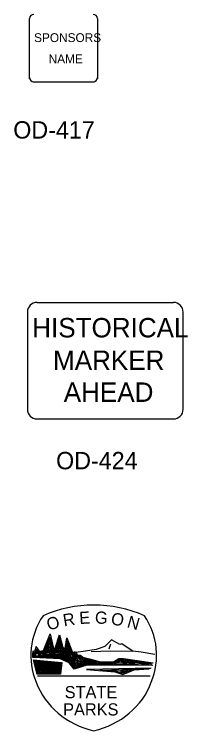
# Model space of a CAD drawing. Extents: x 42133 to 45533, y 41351 to 47951.
# Drawn here: x 42779.6 to 42854.3, y 44951.7 to 45261.2 of the extents above; entities that cross this region are included whole.
import ezdxf

# ---------------------------------------------------------------- set-up
doc = ezdxf.new("R2010")
doc.units = 0
doc.layers.add('P_TRAF_SIGN_SignDetails', color=7, linetype='Continuous')

msp = doc.modelspace()

# ---------------------------------------------------------------- linework, layer by layer
at = {"layer": 'P_TRAF_SIGN_SignDetails'}
for p, q in [((42786.11, 45233.28), (42786.11, 45259.36)), ((42815.43, 45259.36), (42815.43, 45233.33)), ((42787.69, 45232.03), (42814.06, 45232.03)), ((42789.42, 45136.71), (42848.16, 45136.71)), ((42785.22, 45132.52), (42785.22, 45090.56)), ((42852.35, 45090.56), (42852.35, 45132.52)), ((42789.42, 45086.36), (42848.16, 45086.36)), ((42792.22, 44986.34), (42795.01, 44993.48)), ((42794.9, 44992.08), (42792.65, 44986.21)), ((42794.79, 44990.77), (42793.04, 44985.99)), ((42796.31, 44986.62), (42794.79, 44990.77)), ((42796.36, 44986.93), (42794.9, 44992.08)), ((42795.01, 44993.48), (42796.55, 44987.19)), ((42797.19, 44987.33), (42799.06, 44993.15)), ((42798.95, 44991.87), (42797.43, 44987.04)), ((42800.25, 44987.19), (42798.95, 44991.87)), ((42799.06, 44993.15), (42800.53, 44987.58)), ((42801.51, 44987.12), (42802.17, 44991.83)), ((42802.17, 44991.83), (42804.7, 44985.42)), ((42821.53, 44990.96), (42818.54, 44988.02)), ((42825, 44988.87), (42821.53, 44990.96)), ((42789.03, 44988.1), (42788.36, 44985.91)), ((42790.38, 44986.03), (42789.03, 44988.1)), ((42794.74, 44989.58), (42793.33, 44985.74)), ((42794.74, 44988.02), (42793.83, 44985.68)), ((42796.03, 44986.21), (42794.74, 44989.58)), ((42795.86, 44985.88), (42794.74, 44988.02)), ((42798.95, 44990.63), (42797.83, 44986.93)), ((42798.95, 44989.38), (42798.11, 44986.77)), ((42798.84, 44988.12), (42798.56, 44986.46)), ((42799.63, 44985.94), (42798.84, 44988.12)), ((42800.14, 44986.73), (42798.95, 44990.63)), ((42799.85, 44986.35), (42798.95, 44989.38)), ((42802.22, 44990.41), (42801.77, 44986.73)), ((42802.33, 44989.27), (42802.11, 44986.46)), ((42804.36, 44985.11), (42802.22, 44990.41)), ((42804.18, 44984.85), (42802.33, 44989.27)), ((42818.54, 44988.02), (42814.86, 44986.71)), ((42820.46, 44987.03), (42821.17, 44989.26)), ((42825.99, 44989.18), (42825, 44988.87)), ((42828.62, 44987.35), (42825.99, 44989.18)), ((42788.66, 44985.64), (42787.37, 44985.26)), ((42787.37, 44985.26), (42787.48, 44983.45)), ((42788.36, 44985.91), (42787.45, 44985.81)), ((42788.66, 44985.32), (42787.76, 44985)), ((42787.76, 44985), (42787.82, 44983.7)), ((42788.83, 44985), (42788.15, 44984.85)), ((42788.15, 44984.85), (42788.15, 44983.97)), ((42789.39, 44984.8), (42788.49, 44984.64)), ((42788.49, 44984.64), (42788.71, 44984.17)), ((42789.11, 44986.77), (42788.66, 44985.64)), ((42789.28, 44986.05), (42788.66, 44985.32)), ((42789.5, 44985.47), (42788.83, 44985)), ((42790.46, 44985.74), (42789.11, 44986.77)), ((42790.34, 44985.43), (42789.28, 44986.05)), ((42790.51, 44984.8), (42789.39, 44984.8)), ((42790.34, 44985.11), (42789.5, 44985.47)), ((42794.29, 44985.52), (42789.9, 44984.49)), ((42793.04, 44985.99), (42790.34, 44985.43)), ((42793.33, 44985.74), (42790.34, 44985.11)), ((42790.38, 44986.03), (42792.22, 44986.34)), ((42792.65, 44986.21), (42790.46, 44985.74)), ((42793.83, 44985.68), (42790.51, 44984.8)), ((42794.4, 44985.26), (42791.7, 44984.59)), ((42791.7, 44984.59), (42799.52, 44984.59)), ((42794.85, 44986.73), (42794.29, 44985.52)), ((42794.85, 44985.88), (42794.4, 44985.26)), ((42794.96, 44985.05), (42794.45, 44984.85)), ((42794.45, 44984.85), (42798.11, 44984.95)), ((42795.75, 44985.52), (42794.85, 44986.73)), ((42795.58, 44985.32), (42794.85, 44985.88)), ((42798.44, 44985.47), (42794.96, 44985.05)), ((42798.73, 44985.94), (42795.58, 44985.32)), ((42799.07, 44986.31), (42795.75, 44985.52)), ((42798.56, 44986.46), (42795.86, 44985.88)), ((42798.11, 44986.77), (42796.03, 44986.21)), ((42797.83, 44986.93), (42796.31, 44986.62)), ((42797.43, 44987.04), (42796.36, 44986.93)), ((42796.55, 44987.19), (42797.19, 44987.33)), ((42798.11, 44984.95), (42800.03, 44984.75)), ((42799.24, 44985), (42798.44, 44985.47)), ((42799.07, 44985.32), (42798.73, 44985.94)), ((42799.4, 44985.64), (42799.07, 44986.31)), ((42802.45, 44985.11), (42799.07, 44985.32)), ((42802.16, 44984.75), (42799.24, 44985)), ((42802.83, 44985.43), (42799.4, 44985.64)), ((42799.52, 44984.59), (42803.01, 44983.55)), ((42802.78, 44985.74), (42799.63, 44985.94)), ((42802.45, 44986.1), (42799.85, 44986.35)), ((42800.03, 44984.75), (42802.61, 44983.91)), ((42802.11, 44986.46), (42800.14, 44986.73)), ((42801.77, 44986.73), (42800.25, 44987.19)), ((42800.53, 44987.58), (42801.51, 44987.12)), ((42803.01, 44983.55), (42802.16, 44984.75)), ((42802.56, 44987.5), (42802.45, 44986.1)), ((42803.4, 44983.6), (42802.45, 44985.11)), ((42804.02, 44984.54), (42802.56, 44987.5)), ((42803.73, 44984.12), (42802.78, 44986.31)), ((42802.78, 44986.31), (42802.78, 44985.74)), ((42803.34, 44983.81), (42802.83, 44985.43)), ((42805.25, 44984.64), (42804.02, 44984.54)), ((42805.48, 44985.05), (42804.18, 44984.85)), ((42805.59, 44985.47), (42804.36, 44985.11)), ((42804.7, 44985.42), (42805.91, 44985.81)), ((42805.48, 44984.23), (42805.25, 44984.64)), ((42805.88, 44984.28), (42805.48, 44985.05)), ((42806.27, 44984.28), (42805.59, 44985.47)), ((42805.91, 44985.81), (42806.83, 44984.36)), ((42810.23, 44986), (42806.05, 44985.41)), ((42814.86, 44986.71), (42810.23, 44986)), ((42821.02, 44985.98), (42812.65, 44985.8)), ((42830.53, 44985.9), (42821.02, 44985.98)), ((42830.67, 44985.97), (42828.62, 44987.35)), ((42834.21, 44985.64), (42830.67, 44985.97)), ((42840.15, 44984.56), (42834.21, 44985.64)), ((42787.48, 44983.45), (42799.46, 44983.03)), ((42799.3, 44982.67), (42787.55, 44983.24)), ((42787.67, 44982.31), (42800.01, 44981.17)), ((42787.67, 44982.31), (42789.37, 44976.13)), ((42787.82, 44983.7), (42799.57, 44983.34)), ((42787.99, 44982), (42799.78, 44980.95)), ((42789.65, 44976.28), (42788.12, 44981.76)), ((42788.12, 44981.76), (42799.48, 44980.75)), ((42788.15, 44983.97), (42799.8, 44983.6)), ((42789.96, 44976.52), (42788.47, 44981.45)), ((42788.47, 44981.45), (42799.15, 44980.49)), ((42788.71, 44984.17), (42799.74, 44983.87)), ((42789.9, 44984.49), (42799.74, 44984.23)), ((42803.27, 44981.03), (42799.3, 44982.67)), ((42799.46, 44983.03), (42803.01, 44981.42)), ((42799.57, 44983.34), (42803.12, 44981.94)), ((42799.74, 44984.23), (42803.17, 44983.23)), ((42799.74, 44983.87), (42803.12, 44982.98)), ((42799.8, 44983.6), (42803.17, 44982.46)), ((42802.16, 44984.38), (42801.37, 44984.33)), ((42802.61, 44983.91), (42802.16, 44984.38)), ((42803.01, 44981.42), (42805.88, 44984.28)), ((42803.12, 44981.94), (42805.48, 44984.23)), ((42803.12, 44982.98), (42803.96, 44983.81)), ((42803.17, 44982.46), (42805.03, 44984.17)), ((42803.17, 44983.23), (42803.4, 44983.6)), ((42803.96, 44983.81), (42803.34, 44983.81)), ((42803.46, 44981.63), (42806.27, 44984.28)), ((42803.53, 44981.17), (42806.52, 44984.22)), ((42804.81, 44984.28), (42803.73, 44984.12)), ((42804.03, 44981.11), (42806.39, 44983.88)), ((42804.53, 44981.23), (42806.64, 44983.53)), ((42805.03, 44984.17), (42804.81, 44984.28)), ((42804.9, 44981.23), (42806.58, 44982.96)), ((42805.34, 44981.23), (42806.33, 44982.33)), ((42806.08, 44981.06), (42806.33, 44981.46)), ((42806.33, 44982.33), (42806.58, 44981.64)), ((42811, 44981.46), (42806.33, 44980.08)), ((42806.33, 44981.46), (42806.52, 44981)), ((42806.39, 44983.88), (42807.08, 44983.81)), ((42806.52, 44984.22), (42807.57, 44984.05)), ((42806.58, 44982.96), (42807.08, 44981.98)), ((42806.58, 44981.64), (42809.13, 44981.35)), ((42806.64, 44983.53), (42807.82, 44982.38)), ((42806.83, 44984.36), (42808.18, 44984.23)), ((42807.08, 44983.81), (42808.31, 44982.84)), ((42807.08, 44981.98), (42811, 44981.46)), ((42807.57, 44984.05), (42808.82, 44983.01)), ((42807.82, 44982.38), (42812.87, 44981.41)), ((42808.18, 44984.23), (42809.09, 44983.45)), ((42808.31, 44982.84), (42815.3, 44981.17)), ((42808.82, 44983.01), (42816.41, 44981.28)), ((42809.09, 44983.45), (42812, 44982.65)), ((42812, 44982.65), (42816.11, 44981.53)), ((42816.11, 44981.53), (42822.28, 44981.4)), ((42822.28, 44981.4), (42824.63, 44982.83)), ((42825.13, 44982.49), (42823.07, 44981.41)), ((42825.44, 44982.1), (42823.38, 44981.28)), ((42825.68, 44981.75), (42823.7, 44981.06)), ((42824.63, 44982.83), (42826.61, 44982.9)), ((42827.06, 44982.44), (42825.13, 44982.49)), ((42827.06, 44981.98), (42825.44, 44982.1)), ((42837.75, 44980.19), (42825.68, 44981.75)), ((42826.61, 44982.9), (42839.46, 44980.97)), ((42839.07, 44980.71), (42827.06, 44982.44)), ((42838.69, 44980.42), (42827.06, 44981.98)), ((42790.28, 44976.72), (42788.89, 44981.19)), ((42788.89, 44981.19), (42798.91, 44980.24)), ((42790.65, 44977), (42789.28, 44980.85)), ((42789.28, 44980.85), (42798.55, 44979.98)), ((42791.02, 44977.32), (42789.65, 44980.55)), ((42789.65, 44980.55), (42798.26, 44979.72)), ((42791.33, 44977.63), (42790.08, 44980.24)), ((42790.08, 44980.24), (42797.97, 44979.52)), ((42791.58, 44977.95), (42790.49, 44979.93)), ((42790.49, 44979.93), (42797.61, 44979.34)), ((42791.76, 44978.19), (42790.89, 44979.69)), ((42790.89, 44979.69), (42797.32, 44979.16)), ((42791.88, 44978.37), (42791.26, 44979.46)), ((42791.26, 44979.46), (42797.06, 44979)), ((42792.24, 44978.56), (42791.7, 44979.16)), ((42791.7, 44979.16), (42796.88, 44978.85)), ((42797.23, 44978.27), (42791.88, 44978.37)), ((42796.99, 44978.51), (42792.24, 44978.56)), ((42792.55, 44978.69), (42792.28, 44978.87)), ((42792.28, 44978.87), (42795.21, 44978.84)), ((42796.82, 44978.68), (42792.55, 44978.69)), ((42796.88, 44978.85), (42796.82, 44978.68)), ((42797.06, 44979), (42796.99, 44978.51)), ((42797.32, 44979.16), (42797.23, 44978.27)), ((42797.61, 44979.34), (42797.34, 44978.07)), ((42797.97, 44979.52), (42797.65, 44977.83)), ((42798.26, 44979.72), (42797.93, 44977.63)), ((42798.55, 44979.98), (42798.21, 44977.42)), ((42798.91, 44980.24), (42798.45, 44977.16)), ((42799.15, 44980.49), (42798.74, 44976.92)), ((42799.48, 44980.75), (42798.98, 44976.62)), ((42799.78, 44980.95), (42799.15, 44976.31)), ((42800.01, 44981.17), (42799.43, 44976.12)), ((42805.46, 44978.28), (42803.27, 44981.03)), ((42805.58, 44978.64), (42803.53, 44981.17)), ((42805.65, 44978.99), (42804.03, 44981.11)), ((42805.83, 44979.39), (42804.53, 44981.23)), ((42806.01, 44979.68), (42804.9, 44981.23)), ((42806.33, 44980.08), (42805.34, 44981.23)), ((42810.78, 44980.04), (42805.46, 44978.28)), ((42810.75, 44980.31), (42805.58, 44978.64)), ((42810.87, 44980.65), (42805.65, 44978.99)), ((42811.06, 44980.94), (42805.83, 44979.39)), ((42811, 44981.11), (42806.01, 44979.68)), ((42806.39, 44980.54), (42806.08, 44981.06)), ((42809.13, 44981.35), (42806.39, 44980.54)), ((42806.52, 44981), (42807.39, 44981.23)), ((42838.51, 44978.71), (42810.71, 44978.14)), ((42822.39, 44980.25), (42810.75, 44980.31)), ((42817.1, 44980.03), (42810.78, 44980.04)), ((42815.92, 44980.65), (42810.87, 44980.65)), ((42812.87, 44981.41), (42811, 44981.11)), ((42815.3, 44981.17), (42811.06, 44980.94)), ((42815.92, 44981.28), (42815.92, 44980.65)), ((42816.22, 44981.17), (42821.89, 44980.77)), ((42816.47, 44981.35), (42822.63, 44981.11)), ((42816.47, 44980.6), (42816.54, 44980.82)), ((42821.76, 44980.54), (42816.47, 44980.6)), ((42816.54, 44980.82), (42818.71, 44980.77)), ((42816.57, 44977.88), (42835.8, 44978.45)), ((42839.31, 44979.77), (42817.1, 44980.03)), ((42821.89, 44980.77), (42821.76, 44980.54)), ((42822.63, 44981.11), (42822.39, 44980.25)), ((42823.07, 44981.41), (42822.94, 44980.14)), ((42822.94, 44980.14), (42838.63, 44980.02)), ((42823.38, 44981.28), (42823.38, 44980.54)), ((42823.38, 44980.54), (42837.75, 44980.19)), ((42823.7, 44981.06), (42831.72, 44980.65)), ((42831.72, 44980.65), (42825.8, 44981.28)), ((42835.8, 44978.45), (42830.63, 44978.04)), ((42831.31, 44977.99), (42837.55, 44978.35)), ((42837.55, 44978.35), (42838.34, 44978.71)), ((42838.63, 44980.02), (42838.69, 44980.42)), ((42799.43, 44976.12), (42789.37, 44976.13)), ((42789.6, 44975.34), (42838.12, 44975.34)), ((42799.15, 44976.31), (42789.65, 44976.28)), ((42798.98, 44976.62), (42789.96, 44976.52)), ((42798.74, 44976.92), (42790.28, 44976.72)), ((42798.45, 44977.16), (42790.65, 44977)), ((42798.21, 44977.42), (42791.02, 44977.32)), ((42797.93, 44977.63), (42791.33, 44977.63)), ((42797.65, 44977.83), (42791.58, 44977.95)), ((42797.34, 44978.07), (42791.76, 44978.19)), ((42810.71, 44978.14), (42822.98, 44977.1)), ((42822.75, 44977.36), (42816.45, 44977.88)), ((42828.66, 44977.88), (42822.36, 44977.73)), ((42822.36, 44977.73), (42824.27, 44977.26)), ((42826.07, 44976.38), (42822.75, 44977.36)), ((42822.98, 44977.1), (42826.41, 44975.95)), ((42824.27, 44977.26), (42826.36, 44976.74)), ((42825.4, 44977.47), (42826.97, 44977.52)), ((42826.24, 44977.06), (42825.46, 44977.47)), ((42830.63, 44978.04), (42826.07, 44976.38)), ((42826.97, 44977.52), (42826.24, 44977.06)), ((42826.36, 44976.74), (42828.66, 44977.83)), ((42826.41, 44975.95), (42831.31, 44977.99))]:
    msp.add_line(p, q, dxfattribs=at)
for centre, start, end in [((42787.95, 45259.35), 90, 180), ((42813.61, 45259.35), 0, 90), ((42787.95, 45233.87), 180, 270), ((42813.61, 45233.87), 270, 0)]:
    msp.add_arc(centre, 1.83, start, end, dxfattribs=at)
for centre, major_axis, ratio, start_param, end_param in [((42789.42, 45132.52), (0, 4.2), 0.9998, 0, 1.570796), ((42848.16, 45132.52), (0, 4.2), 0.9998, 4.712389, 6.283185), ((42789.42, 45090.55), (0, -4.2), 0.9998, 4.712389, 6.283185), ((42848.16, 45090.55), (0, 4.2), 0.9998, 3.141593, 4.712389), ((42813.82, 44958.78), (-50.99, 0), 0.924214, 4.269316, 5.155462), ((42822.05, 44984.23), (35.34, 0), 0.924214, 2.589582, 3.503628), ((42805.59, 44984.23), (35.34, 0), 0.924214, 5.921149, 6.835196), ((42822.03, 44982.99), (34.87, 0), 0.924214, 3.467853, 4.474694), ((42805.61, 44982.99), (34.87, 0), 0.924214, 4.950084, 5.956925)]:
    msp.add_ellipse(centre, major_axis=major_axis, ratio=ratio, start_param=start_param, end_param=end_param, dxfattribs=at)

# ---------------------------------------------------------------- texts
for s, height, p in [('SPONSORS', 3.812, (42788.12, 45249.2)), ('NAME', 3.812, (42794.39, 45240.03)), ('OD-417', 7.5, (42779.14, 45207.5)), ('HISTORICAL', 8.393, (42787.31, 45121.59)), ('MARKER', 8.393, (42796.28, 45107.53)), ('AHEAD', 8.393, (42800.89, 45093.74)), ('OD-424', 7.5, (42797.6, 45064.61)), ('STATE', 5.257, (42801.31, 44965.69)), ('PARKS', 5.257, (42800.64, 44958.23))]:
    msp.add_text(s, height=height, dxfattribs=at).set_placement(p)
for s, rotation, p in [('E', 3.3723, (42807.73, 44997.72)), ('G', 357.0643, (42814.23, 44998.01)), ('O', 15.9197, (42794.36, 44994.88)), ('R', 9.6723, (42801.04, 44996.69)), ('O', 350.6297, (42821, 44997.62)), ('N', 344.2172, (42827.84, 44996.43))]:
    msp.add_text(s, height=5.26, rotation=rotation, dxfattribs=at).set_placement(p)

doc.saveas('drawing.dxf')
